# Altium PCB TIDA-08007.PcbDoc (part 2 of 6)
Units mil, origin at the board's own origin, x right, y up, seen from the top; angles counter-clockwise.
Board outline 4212.6 x 2047.24 mil, 10 copper layers (Top Layer, GND 1, Signal Layer 1, GND 2, Split PWR 1, Split PWR 2, GND 3, Signal Layer 2, GND 4, Bottom Layer), stack 66.4 mil thick; 291 components, 178 nets, 1281 pads, 873 vias.
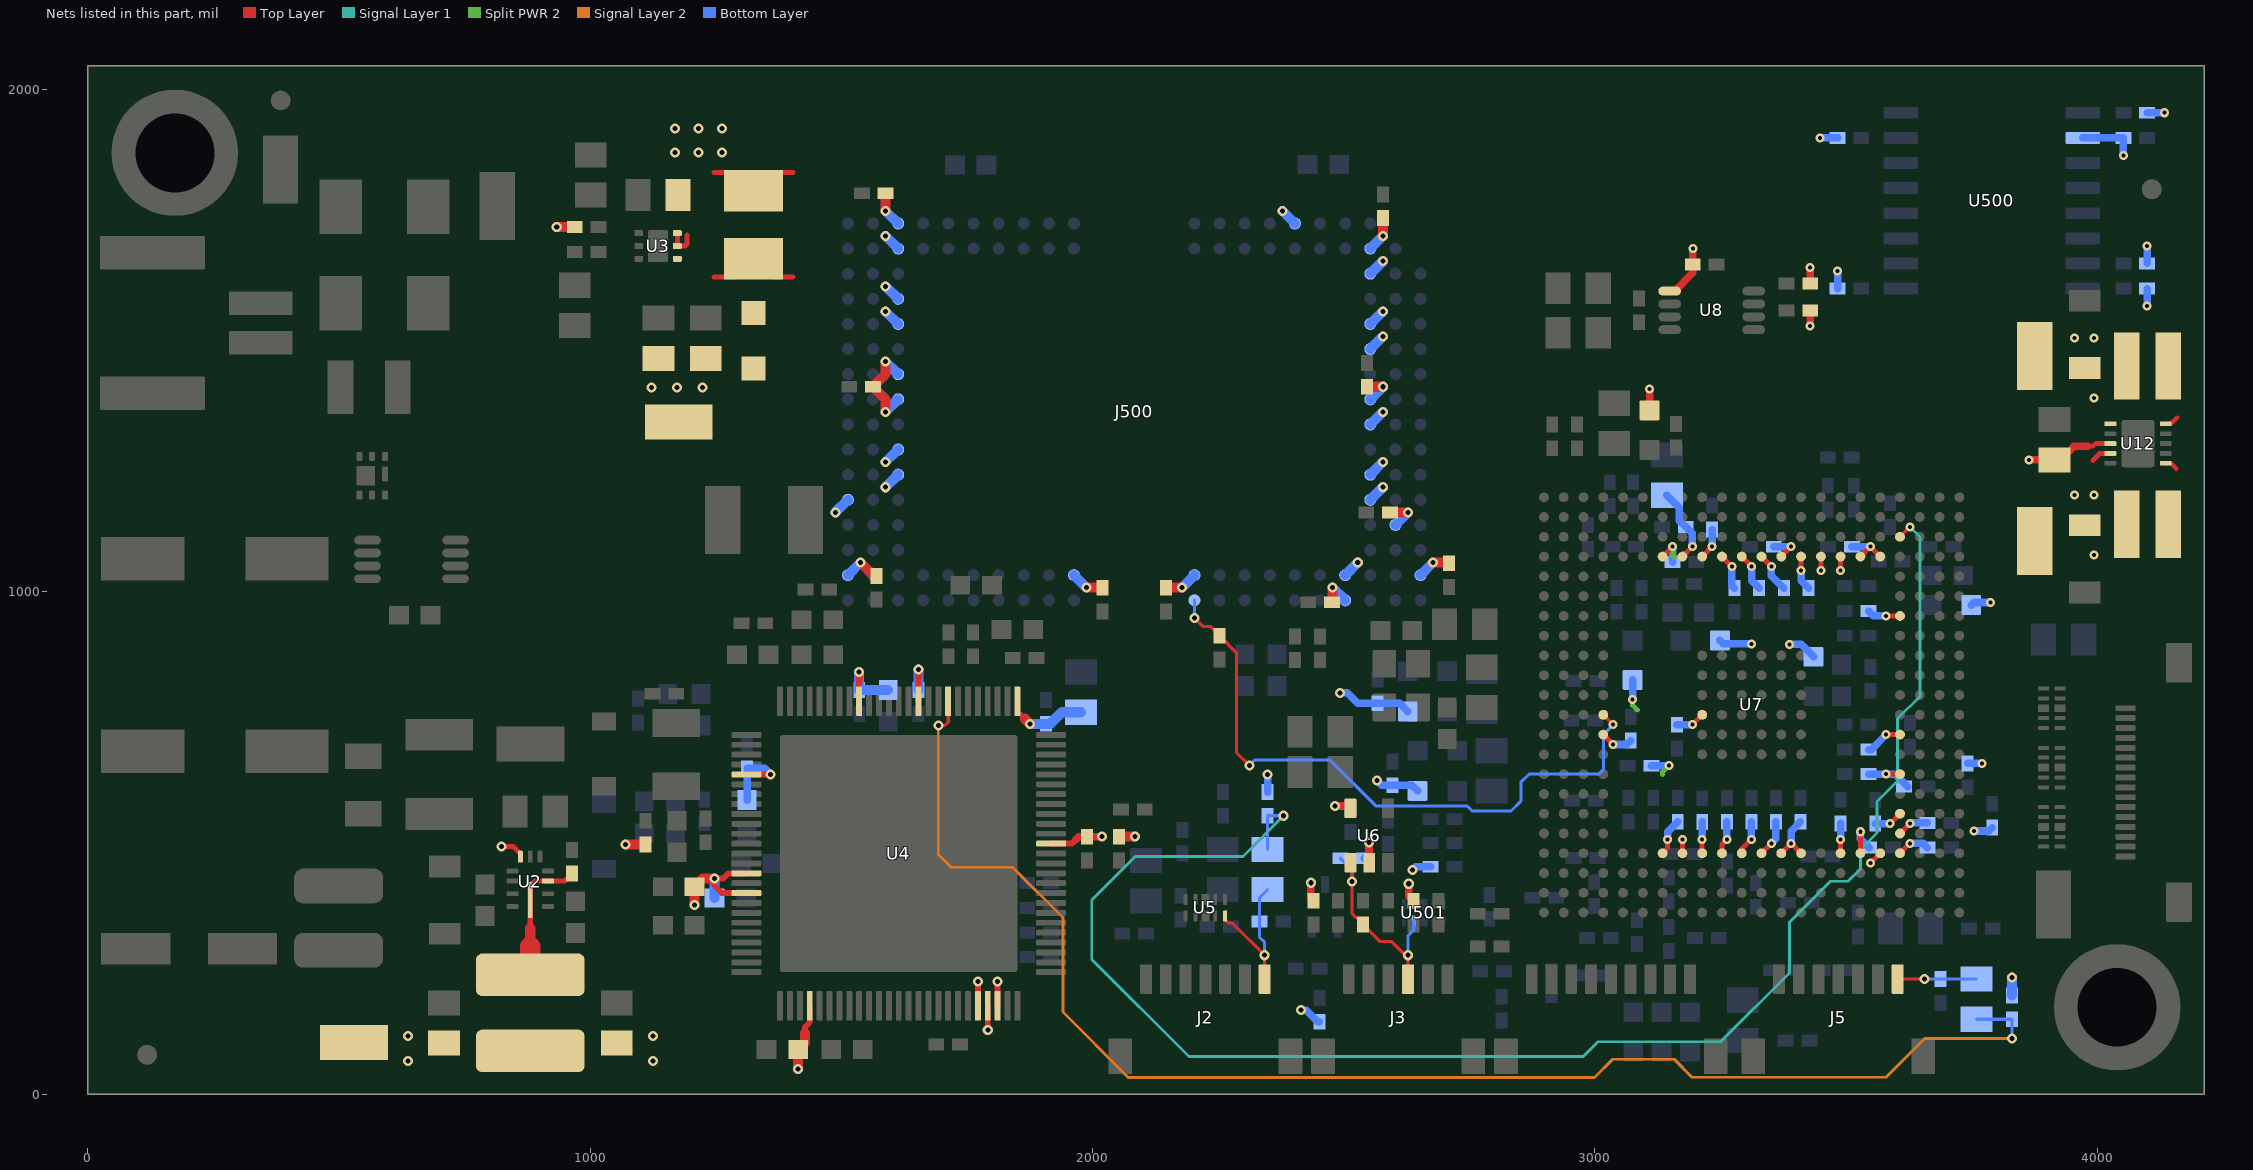
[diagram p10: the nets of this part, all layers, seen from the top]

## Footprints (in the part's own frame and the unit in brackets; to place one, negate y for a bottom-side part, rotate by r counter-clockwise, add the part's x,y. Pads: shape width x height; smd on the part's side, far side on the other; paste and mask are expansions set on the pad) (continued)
FP-450-2.700-L-13.25-149_SOCKET_CPGA149-MFG [mm]
  round 0.61 smd paste+0 mask+0: A3(-11.935,9.525) A4(-10.665,9.525) A5(-9.395,9.525) A6(-8.125,9.525) A7(-6.855,9.525) A8(-5.585,9.525) A9(-4.315,9.525) A10(-3.045,9.525) A11(3.045,9.525) A12(4.315,9.525) A13(5.585,9.525) A14(6.855,9.525) A15(8.125,9.525) A16(9.395,9.525) A17(10.665,9.525) A18(11.935,9.525) A19(13.205,9.525) A20(14.475,9.525) B2(-13.205,8.255) B3(-11.935,8.255) B4(-10.665,8.255) B5(-9.395,8.255) B6(-8.125,8.255) B7(-6.855,8.255) B8(-5.585,8.255) B9(-4.315,8.255) B10(-3.045,8.255) B11(3.045,8.255) B12(4.315,8.255) B13(5.585,8.255) B14(6.855,8.255) B15(8.125,8.255) B16(9.395,8.255) B17(10.665,8.255) B18(11.935,8.255) B19(13.205,8.255) B20(14.475,8.255) C1(-14.475,6.985) C2(-13.205,6.985) C3(-11.935,6.985) C18(11.935,6.985) C19(13.205,6.985) C20(14.475,6.985) D1(-14.475,5.715) D2(-13.205,5.715) D3(-11.935,5.715) D18(11.935,5.715) D19(13.205,5.715) D20(14.475,5.715) E1(-14.475,4.445) E2(-13.205,4.445) E3(-11.935,4.445) E18(11.935,4.445) E19(13.205,4.445) E20(14.475,4.445) F1(-14.475,3.175) F2(-13.205,3.175) F3(-11.935,3.175) F18(11.935,3.175) F19(13.205,3.175) F20(14.475,3.175) G1(-14.475,1.905) G2(-13.205,1.905) G3(-11.935,1.905) G18(11.935,1.905) G19(13.205,1.905) G20(14.475,1.905) H1(-14.475,0.635) H2(-13.205,0.635) H3(-11.935,0.635) H18(11.935,0.635) H19(13.205,0.635) H20(14.475,0.635) J1(-14.475,-0.635) J2(-13.205,-0.635) J3(-11.935,-0.635) J18(11.935,-0.635) J19(13.205,-0.635) J20(14.475,-0.635) K1(-14.475,-1.905) K2(-13.205,-1.905) K3(-11.935,-1.905) K18(11.935,-1.905) K19(13.205,-1.905) K20(14.475,-1.905) L1(-14.475,-3.175) L2(-13.205,-3.175) L3(-11.935,-3.175) L18(11.935,-3.175) L19(13.205,-3.175) L20(14.475,-3.175) M1(-14.475,-4.445) M2(-13.205,-4.445) M3(-11.935,-4.445) M18(11.935,-4.445) M19(13.205,-4.445) M20(14.475,-4.445) N1(-14.475,-5.715) N2(-13.205,-5.715) N3(-11.935,-5.715) N18(11.935,-5.715) N19(13.205,-5.715) N20(14.475,-5.715) P1(-14.475,-6.985) P2(-13.205,-6.985) P3(-11.935,-6.985) P18(11.935,-6.985) P19(13.205,-6.985) P20(14.475,-6.985) R1(-14.475,-8.255) R2(-13.205,-8.255) R3(-11.935,-8.255) R4(-10.665,-8.255) R5(-9.395,-8.255) R6(-8.125,-8.255) R7(-6.855,-8.255) R8(-5.585,-8.255) R9(-4.315,-8.255) R10(-3.045,-8.255) R11(3.045,-8.255) R12(4.315,-8.255) R13(5.585,-8.255) R14(6.855,-8.255) R15(8.125,-8.255) R16(9.395,-8.255) R17(10.665,-8.255) R18(11.935,-8.255) R19(13.205,-8.255) R20(14.475,-8.255) T1(-14.475,-9.525) T2(-13.205,-9.525) T3(-11.935,-9.525) T4(-10.665,-9.525) T5(-9.395,-9.525) T6(-8.125,-9.525) T7(-6.855,-9.525) T8(-5.585,-9.525) T9(-4.315,-9.525) T10(-3.045,-9.525) T11(3.045,-9.525) T12(4.315,-9.525) T13(5.585,-9.525) T14(6.855,-9.525) T15(8.125,-9.525) T16(9.395,-9.525) T17(10.665,-9.525) T18(11.935,-9.525) T19(13.205,-9.525) T20(14.475,-9.525)
  body extent -16.1,-11.15 16.1,11.15, height 2.9
FP-203559-0607_HDR6-MFG [mm]
  rrect17% 0.6x1.5 smd paste-1000 mask+0: 1(-2.5,2.825) 2(-1.5,2.825) 3(-0.5,2.825) 4(0.5,2.825) 5(1.5,2.825) 6(2.5,2.825)
  rrect8% 1.2x1.8 smd paste-1000 mask+0: 7(-3.8,-1.075) 8(3.8,-1.075)
  Top Layer keep-out region: -3.35,-2.975 3.35,-2.975 3.35,2.675 -3.35,2.675
  body extent -4.5,-2.98 4.5,3.67, height 0.25
FP-501568-0707_HDR7-MFG [mm]
  rrect17% 0.6x1.5 smd paste-1000 mask+0: 1(-3,2.825) 2(-2,2.825) 3(-1,2.825) 4(0,2.825) 5(1,2.825) 6(2,2.825) 7(3,2.825)
  rrect8% 1.2x1.8 smd paste-1000 mask+0: 8(-4.3,-1.075) 9(4.3,-1.075)
  Top Layer keep-out region: -3.85,-2.975 3.85,-2.975 3.85,2.675 -3.85,2.675
  body extent -5,-2.98 5,3.67, height 0.25
FP-501568-0907_HDR9-MFG [mm]
  rrect17% 0.6x1.5 smd paste-1000 mask+0: 1(-4,2.825) 2(-3,2.825) 3(-2,2.825) 4(-1,2.825) 5(0,2.825) 6(1,2.825) 7(2,2.825) 8(3,2.825) 9(4,2.825)
  rrect8% 1.2x1.8 smd paste-1000 mask+0: 10(-5.3,-1.075) 11(5.3,-1.075)
  Top Layer keep-out region: -4.85,-2.975 4.85,-2.975 4.85,2.675 -4.85,2.675
  body extent -6,-2.98 6,3.67, height 0.25
FP-502352-0200_HDR2-MFG [mm]
  rrect8% 1.2x3.2 smd paste+0 mask+0: 1(-1,3.53) 2(1,3.53)
  rrect6% 1.7x5.3 smd paste+0 mask+0: 3(-3.55,-1.95) 4(3.55,-1.95)
  body extent -4.5,-4.9 4.5,5.23, height 0.25
FP-505110-1692_CONN_SMT_12MM7_5MM25-MFG [mm]
  rrect33% 0.3x1 smd paste+0 mask+0: 1(-3.75,2.475) 2(-3.25,2.475) 3(-2.75,2.475) 4(-2.25,2.475) 5(-1.75,2.475) 6(-1.25,2.475) 7(-0.75,2.475) 8(-0.25,2.475) 9(0.25,2.475) 10(0.75,2.475) 11(1.25,2.475) 12(1.75,2.475) 13(2.25,2.475) 14(2.75,2.475) 15(3.25,2.475) 16(3.75,2.475)
  rrect8% 2x1.3 smd paste+0 mask+0: 17(-6.05,-0.225) 18(6.05,-0.225)
  body extent -7.15,-2.83 7.15,3.08, height 0.25
FP-AM16070006_SMT_XTAL_3MM2_2MM5-MFG [mm]
  rrect8% 1.4x1.2 smd paste+0 mask+0: 1(-1.1,-0.85) 2(1.1,-0.85) 3(1.1,0.85) 4(-1.1,0.85)
  body extent -1.6,-1.25 1.6,1.25, height 0.8
FP-FBMH1608HM101-TV_0603-MFG [mm]
  rrect10% 1x1 smd paste+0 mask+0: 1(-1,0) 2(1,0)
  body extent -0.8,-0.4 0.8,0.4, height 0.9
FP-MT25QL128ABA8ESF-0AAT_SOP2-16-MFG [mm]
  rrect17% 1.75x0.6 smd paste+0 mask+0: 1(-4.6,4.445) 2(-4.6,3.175) 3(-4.6,1.905) 4(-4.6,0.635) 5(-4.6,-0.635) 6(-4.6,-1.905) 7(-4.6,-3.175) 8(-4.6,-4.445) 9(4.6,-4.445) 10(4.6,-3.175) 11(4.6,-1.905) 12(4.6,-0.635) 13(4.6,0.635) 14(4.6,1.905) 15(4.6,3.175) 16(4.6,4.445)
  body extent -5.16,-5.15 5.16,5.15, height 2.65
MTGP_252mil_157mil_6Via [mil] "4-40 Mounting Hole, Plated, for Pan Head"
  round 252 hole 157: 1(0,0)
PZP0100K [mm] "TQFP-100"
  rrect33% 1.5x0.3 smd: 1(-7.7,6) 2(-7.7,5.5) 3(-7.7,5) 4(-7.7,4.5) 5(-7.7,4) 6(-7.7,3.5) 7(-7.7,3) 8(-7.7,2.5) 9(-7.7,2) 10(-7.7,1.5) 11(-7.7,1) 12(-7.7,0.5) 13(-7.7,0) 14(-7.7,-0.5) 15(-7.7,-1) 16(-7.7,-1.5) 17(-7.7,-2) 18(-7.7,-2.5) 19(-7.7,-3) 20(-7.7,-3.5) 21(-7.7,-4) 22(-7.7,-4.5) 23(-7.7,-5) 24(-7.7,-5.5) 25(-7.7,-6) 51(7.7,-6) 52(7.7,-5.5) 53(7.7,-5) 54(7.7,-4.5) 55(7.7,-4) 56(7.7,-3.5) 57(7.7,-3) 58(7.7,-2.5) 59(7.7,-2) 60(7.7,-1.5) 61(7.7,-1) 62(7.7,-0.5) 63(7.7,0) 64(7.7,0.5) 65(7.7,1) 66(7.7,1.5) 67(7.7,2) 68(7.7,2.5) 69(7.7,3) 70(7.7,3.5) 71(7.7,4) 72(7.7,4.5) 73(7.7,5) 74(7.7,5.5) 75(7.7,6)
  rrect33% 0.3x1.5 smd: 26(-6,-7.7) 27(-5.5,-7.7) 28(-5,-7.7) 29(-4.5,-7.7) 30(-4,-7.7) 31(-3.5,-7.7) 32(-3,-7.7) 33(-2.5,-7.7) 34(-2,-7.7) 35(-1.5,-7.7) 36(-1,-7.7) 37(-0.5,-7.7) 38(0,-7.7) 39(0.5,-7.7) 40(1,-7.7) 41(1.5,-7.7) 42(2,-7.7) 43(2.5,-7.7) 44(3,-7.7) 45(3.5,-7.7) 46(4,-7.7) 47(4.5,-7.7) 48(5,-7.7) 49(5.5,-7.7) 50(6,-7.7) 76(6,7.7) 77(5.5,7.7) 78(5,7.7) 79(4.5,7.7) 80(4,7.7) 81(3.5,7.7) 82(3,7.7) 83(2.5,7.7) 84(2,7.7) 85(1.5,7.7) 86(1,7.7) 87(0.5,7.7) 88(0,7.7) 89(-0.5,7.7) 90(-1,7.7) 91(-1.5,7.7) 92(-2,7.7) 93(-2.5,7.7) 94(-3,7.7) 95(-3.5,7.7) 96(-4,7.7) 97(-4.5,7.7) 98(-5,7.7) 99(-5.5,7.7) 100(-6,7.7)
  rrect2% 12x12 smd paste-3 mask-3: 101(0,0)
  body extent -8.01,-8.01 8.01,8.01, height 1.2
RNX0012B [mm] "VQFN-HR-12"
  rrect40% 0.6x0.25 smd: 1(-0.9,1.125) 2(-0.9,0.475) 3(-0.9,-0.175) 4(-0.9,-0.675) 8(0.9,-0.675) 9(0.9,-0.175) 10(0.9,0.475) 11(0.9,1.125)
  rrect40% 0.25x0.6 smd: 5(-0.5,-1.4) 6(0,-1.4) 7(0.5,-1.4)
  rrect40% 0.25x1.825 smd paste-0.175: 12(0,0.788)
  body extent -1,-1.5 1,1.5, height 1
SDE0604A [mm] "BOURNS"
  rrect30% 2.15x5.5 smd: 1(-1.925,0) 2(1.925,0)
  Top Layer region: -0.9,2.75 -1.525,2.75 -1.544,2.746 -1.56,2.735 -1.571,2.719 -1.575,2.7 -1.575,2.7 -1.575,2.5 -1.571,2.481 -1.56,2.465 -1.544,2.454 -1.525,2.45 -1.525,2.45 -0.9,2.45 -0.881,2.454 -0.865,2.465 -0.854,2.481 -0.85,2.5 -0.85,2.5 -0.85,2.7 -0.854,2.719 -0.865,2.735 -0.881,2.746 -0.9,2.75
  Top Layer region: 0.9,2.75 1.525,2.75 1.544,2.746 1.56,2.735 1.571,2.719 1.575,2.7 1.575,2.7 1.575,2.5 1.571,2.481 1.56,2.465 1.544,2.454 1.525,2.45 1.525,2.45 0.9,2.45 0.881,2.454 0.865,2.465 0.854,2.481 0.85,2.5 0.85,2.5 0.85,2.7 0.854,2.719 0.865,2.735 0.881,2.746 0.9,2.75
  Top Layer region: 0.9,-2.75 1.525,-2.75 1.544,-2.746 1.56,-2.735 1.571,-2.719 1.575,-2.7 1.575,-2.7 1.575,-2.5 1.571,-2.481 1.56,-2.465 1.544,-2.454 1.525,-2.45 1.525,-2.45 0.9,-2.45 0.881,-2.454 0.865,-2.465 0.854,-2.481 0.85,-2.5 0.85,-2.5 0.85,-2.7 0.854,-2.719 0.865,-2.735 0.881,-2.746 0.9,-2.75
  Top Layer region: -0.898,-2.75 -1.523,-2.75 -1.542,-2.746 -1.558,-2.735 -1.569,-2.719 -1.573,-2.7 -1.572,-2.7 -1.573,-2.5 -1.569,-2.481 -1.558,-2.465 -1.542,-2.454 -1.523,-2.45 -1.523,-2.45 -0.898,-2.45 -0.878,-2.454 -0.862,-2.465 -0.851,-2.481 -0.848,-2.5 -0.848,-2.5 -0.847,-2.7 -0.851,-2.719 -0.862,-2.735 -0.878,-2.746 -0.898,-2.75
  Top Layer region: -0.85,2.072 -1.05,2.073 -1.05,2.648 -0.85,2.648
  Top Layer region: 0.85,2.043 1.05,2.043 1.05,2.618 0.85,2.618
  Top Layer region: 0.85,-2.102 1.05,-2.103 1.05,-2.678 0.85,-2.678
  Top Layer region: -0.85,-2.143 -1.05,-2.142 -1.05,-2.718 -0.85,-2.718
  silkscreen extent -0.63,-2.84 0.62,2.85, body extent -3.05,-2.74 3.05,2.74, height 4.8
SMB [mil] "Molded Diode, 2-Leads, Body 5.4x3.6mm, IPC Medium Density, based on OnSemi component dimensions"
  rect 85x107.99 smd: 1(-87.01,0) 2(87.01,0)
  silkscreen extent -155,-82 125,82, body extent -106,-71 106,71, height 91
SOD-123 [mm] "On Semi recommended land pattern"
  rect 0.915x1.22 smd: 1(-1.637,0) 2(1.637,0)
  silkscreen extent -2.74,-1.17 2.03,1.17, body extent -1.93,-0.9 1.93,0.9, height 1.35
SOD-123F [mm] "NXP recommended land pattern"
  rect 1.2x1.2 smd paste-0.05: 1(-1.4,0) 2(1.4,0)
  silkscreen extent -2.64,-1.12 2.01,1.12, body extent -1.8,-0.85 1.8,0.85, height 1.2
Testpoint_Keystone_Miniature [mil] "Miniature SMT test point"
  rect 135x70 smd: 1(0,0)
  silkscreen extent -78,-46 78,45, body extent -52,-20 52,20, height 61
TI_Stacked_Overlay_Small [mil]
  silkscreen extent -418,-98 418,98
VLCF5020 [mm] "TDK"
  rect 2.1x3 smd: 1(-1.725,0) 2(1.725,0)
  Top Layer region: -0.675,2.45 -1.875,2.45 -2.775,1.55 -2.775,1.4 -0.675,1.4
  Top Layer region: -0.675,-2.45 -1.875,-2.45 -2.775,-1.55 -2.775,-1.4 -0.675,-1.4
  Top Layer region: 0.675,-2.45 1.875,-2.45 2.775,-1.55 2.775,-1.4 0.675,-1.4
  Top Layer region: 0.675,2.4 1.875,2.4 2.775,1.5 2.775,1.35 0.675,1.35
  body extent -2.6,-2.6 2.6,2.6, height 2
WE-MAIA_3015 [mm] "SMD, 2-Leads, Body 3x3mm"
  rect 1.3x3.4 smd: 1(-1.05,0) 2(1.05,0)
  silkscreen extent -0.1,-1.6 0.1,1.6, body extent -1.6,-1.6 1.6,1.6, height 1.5
WE-PD2-S [mm] "WURTH"
  rrect50% 1.75x4.5 smd: 1(-1.625,0) 2(1.625,0)
  Top Layer region: 1.375,2.25 0.75,2.25 0.75,-2.25 1.375,-2.25
  Top Layer region: -1.375,-2.25 -0.75,-2.25 -0.75,2.25 -1.375,2.25
  silkscreen extent -0.4,-2.1 0.4,2.12, body extent -2.25,-2 2.25,2, height 3.18
WEEE_Minimum [mil] "WEEElie bin"
  silkscreen extent -95,-172 99,104
ZDQ0324 [mm] "BGA-324"
  round 0.5 smd: A1(-10.5,10.5) A2(-9.5,10.5) A3(-8.5,10.5) A4(-7.5,10.5) A5(-6.5,10.5) A6(-5.5,10.5) A7(-4.5,10.5) A8(-3.5,10.5) A9(-2.5,10.5) A10(-1.5,10.5) A11(-0.5,10.5) A12(0.5,10.5) A13(1.5,10.5) A14(2.5,10.5) A15(3.5,10.5) A16(4.5,10.5) A17(5.5,10.5) A18(6.5,10.5) A19(7.5,10.5) A20(8.5,10.5) A21(9.5,10.5) A22(10.5,10.5) AA1(-10.5,-9.5) AA2(-9.5,-9.5) AA3(-8.5,-9.5) AA4(-7.5,-9.5) AA5(-6.5,-9.5) AA6(-5.5,-9.5) AA7(-4.5,-9.5) AA8(-3.5,-9.5) AA9(-2.5,-9.5) AA10(-1.5,-9.5) AA11(-0.5,-9.5) AA12(0.5,-9.5) AA13(1.5,-9.5) AA14(2.5,-9.5) AA15(3.5,-9.5) AA16(4.5,-9.5) AA17(5.5,-9.5) AA18(6.5,-9.5) AA19(7.5,-9.5) AA20(8.5,-9.5) AA21(9.5,-9.5) AA22(10.5,-9.5) AB1(-10.5,-10.5) AB2(-9.5,-10.5) AB3(-8.5,-10.5) AB4(-7.5,-10.5) AB5(-6.5,-10.5) AB6(-5.5,-10.5) AB7(-4.5,-10.5) AB8(-3.5,-10.5) AB9(-2.5,-10.5) AB10(-1.5,-10.5) AB11(-0.5,-10.5) AB12(0.5,-10.5) AB13(1.5,-10.5) AB14(2.5,-10.5) AB15(3.5,-10.5) AB16(4.5,-10.5) AB17(5.5,-10.5) AB18(6.5,-10.5) AB19(7.5,-10.5) AB20(8.5,-10.5) AB21(9.5,-10.5) AB22(10.5,-10.5) B1(-10.5,9.5) B2(-9.5,9.5) B3(-8.5,9.5) B4(-7.5,9.5) B5(-6.5,9.5) B6(-5.5,9.5) B7(-4.5,9.5) B8(-3.5,9.5) B9(-2.5,9.5) B10(-1.5,9.5) B11(-0.5,9.5) B12(0.5,9.5) B13(1.5,9.5) B14(2.5,9.5) B15(3.5,9.5) B16(4.5,9.5) B17(5.5,9.5) B18(6.5,9.5) B19(7.5,9.5) B20(8.5,9.5) B21(9.5,9.5) B22(10.5,9.5) C1(-10.5,8.5) C2(-9.5,8.5) C3(-8.5,8.5) C4(-7.5,8.5) C5(-6.5,8.5) C6(-5.5,8.5) C7(-4.5,8.5) C8(-3.5,8.5) C9(-2.5,8.5) C10(-1.5,8.5) C11(-0.5,8.5) C12(0.5,8.5) C13(1.5,8.5) C14(2.5,8.5) C15(3.5,8.5) C16(4.5,8.5) C17(5.5,8.5) C18(6.5,8.5) C19(7.5,8.5) C20(8.5,8.5) C21(9.5,8.5) C22(10.5,8.5) D1(-10.5,7.5) D2(-9.5,7.5) D3(-8.5,7.5) D4(-7.5,7.5) D5(-6.5,7.5) D6(-5.5,7.5) D7(-4.5,7.5) D8(-3.5,7.5) D9(-2.5,7.5) D10(-1.5,7.5) D11(-0.5,7.5) D12(0.5,7.5) D13(1.5,7.5) D14(2.5,7.5) D15(3.5,7.5) D16(4.5,7.5) D17(5.5,7.5) D18(6.5,7.5) D19(7.5,7.5) D20(8.5,7.5) D21(9.5,7.5) D22(10.5,7.5) E1(-10.5,6.5) E2(-9.5,6.5) E3(-8.5,6.5) E4(-7.5,6.5) E19(7.5,6.5) E20(8.5,6.5) E21(9.5,6.5) E22(10.5,6.5) F1(-10.5,5.5) F2(-9.5,5.5) F3(-8.5,5.5) F4(-7.5,5.5) F19(7.5,5.5) F20(8.5,5.5) F21(9.5,5.5) F22(10.5,5.5) G1(-10.5,4.5) G2(-9.5,4.5) G3(-8.5,4.5) G4(-7.5,4.5) G19(7.5,4.5) G20(8.5,4.5) G21(9.5,4.5) G22(10.5,4.5) H1(-10.5,3.5) H2(-9.5,3.5) H3(-8.5,3.5) H4(-7.5,3.5) H19(7.5,3.5) H20(8.5,3.5) H21(9.5,3.5) H22(10.5,3.5) J1(-10.5,2.5) J2(-9.5,2.5) J3(-8.5,2.5) J4(-7.5,2.5) J9(-2.5,2.5) J10(-1.5,2.5) J11(-0.5,2.5) J12(0.5,2.5) J13(1.5,2.5) J14(2.5,2.5) J19(7.5,2.5) J20(8.5,2.5) J21(9.5,2.5) J22(10.5,2.5) K1(-10.5,1.5) K2(-9.5,1.5) K3(-8.5,1.5) K4(-7.5,1.5) K9(-2.5,1.5) K10(-1.5,1.5) K11(-0.5,1.5) K12(0.5,1.5) K13(1.5,1.5) K14(2.5,1.5) K19(7.5,1.5) K20(8.5,1.5) K21(9.5,1.5) K22(10.5,1.5) L1(-10.5,0.5) L2(-9.5,0.5) L3(-8.5,0.5) L4(-7.5,0.5) L9(-2.5,0.5) L10(-1.5,0.5) L11(-0.5,0.5) L12(0.5,0.5) L13(1.5,0.5) L14(2.5,0.5) L19(7.5,0.5) L20(8.5,0.5) L21(9.5,0.5) L22(10.5,0.5) M1(-10.5,-0.5) M2(-9.5,-0.5) M3(-8.5,-0.5) M4(-7.5,-0.5) M9(-2.5,-0.5) M10(-1.5,-0.5) M11(-0.5,-0.5) M12(0.5,-0.5) M13(1.5,-0.5) M14(2.5,-0.5) M19(7.5,-0.5) M20(8.5,-0.5) M21(9.5,-0.5) M22(10.5,-0.5) N1(-10.5,-1.5) N2(-9.5,-1.5) N3(-8.5,-1.5) N4(-7.5,-1.5) N9(-2.5,-1.5) N10(-1.5,-1.5) N11(-0.5,-1.5) N12(0.5,-1.5) N13(1.5,-1.5) N14(2.5,-1.5) N19(7.5,-1.5) N20(8.5,-1.5) N21(9.5,-1.5) N22(10.5,-1.5) P1(-10.5,-2.5) P2(-9.5,-2.5) P3(-8.5,-2.5) P4(-7.5,-2.5) P9(-2.5,-2.5) P10(-1.5,-2.5) P11(-0.5,-2.5) P12(0.5,-2.5) P13(1.5,-2.5) P14(2.5,-2.5) P19(7.5,-2.5) P20(8.5,-2.5) P21(9.5,-2.5) P22(10.5,-2.5) R1(-10.5,-3.5) R2(-9.5,-3.5) R3(-8.5,-3.5) R4(-7.5,-3.5) R19(7.5,-3.5) R20(8.5,-3.5) R21(9.5,-3.5) R22(10.5,-3.5) T1(-10.5,-4.5) T2(-9.5,-4.5) T3(-8.5,-4.5) T4(-7.5,-4.5) T19(7.5,-4.5) T20(8.5,-4.5) T21(9.5,-4.5) T22(10.5,-4.5) U1(-10.5,-5.5) U2(-9.5,-5.5) U3(-8.5,-5.5) U4(-7.5,-5.5) U19(7.5,-5.5) U20(8.5,-5.5) U21(9.5,-5.5) U22(10.5,-5.5) V1(-10.5,-6.5) V2(-9.5,-6.5) V3(-8.5,-6.5) V4(-7.5,-6.5) V19(7.5,-6.5) V20(8.5,-6.5) V21(9.5,-6.5) V22(10.5,-6.5) W1(-10.5,-7.5) W2(-9.5,-7.5) W3(-8.5,-7.5) W4(-7.5,-7.5) W5(-6.5,-7.5) W6(-5.5,-7.5) W7(-4.5,-7.5) W8(-3.5,-7.5) W9(-2.5,-7.5) W10(-1.5,-7.5) W11(-0.5,-7.5) W12(0.5,-7.5) W13(1.5,-7.5) W14(2.5,-7.5) W15(3.5,-7.5) W16(4.5,-7.5) W17(5.5,-7.5) W18(6.5,-7.5) W19(7.5,-7.5) W20(8.5,-7.5) W21(9.5,-7.5) W22(10.5,-7.5) Y1(-10.5,-8.5) Y2(-9.5,-8.5) Y3(-8.5,-8.5) Y4(-7.5,-8.5) Y5(-6.5,-8.5) Y6(-5.5,-8.5) Y7(-4.5,-8.5) Y8(-3.5,-8.5) Y9(-2.5,-8.5) Y10(-1.5,-8.5) Y11(-0.5,-8.5) Y12(0.5,-8.5) Y13(1.5,-8.5) Y14(2.5,-8.5) Y15(3.5,-8.5) Y16(4.5,-8.5) Y17(5.5,-8.5) Y18(6.5,-8.5) Y19(7.5,-8.5) Y20(8.5,-8.5) Y21(9.5,-8.5) Y22(10.5,-8.5)
  body extent -11.5,-11.5 11.5,11.5, height 2.35

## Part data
C1 C2: library part CMP-0086092-1, "CAP, AL, 220 µF, 50 V, +/- 20%, AEC-Q200 Grade 2, SMD", Cap_Case=HA0, Manufacturer=Chemi-Con, Tolerance_%=20%, Value2=50V, ValueDisplayed=220µF
C3: library part CMP-0011237-3, "CAP, AL, 22 uF, 50 V, +/- 20%, SMD", Cap_Case=F55, Manufacturer=Chemi-Con, Supplier Part Number 1=565-2130-1-ND, Tolerance_%=20%, Value1=Unknown, Value2=50V, ValueDisplayed=22uF
C4: library part CMP-0079201-1, "CAP, CERM, 10 µF, 50 V,+/- 10%, X7R, 1210", Cap_Case=1210, Manufacturer="Samsung Electro-Mechanics", Supplier Part Number 1=1276-3388-1-ND, TempCo=X7R, Tolerance_%=10%, Value1="0.005 ohm", Value2=50V, ValueDisplayed=10µF
C5 C18 C19 C20 C24 C27 C501 C522 C535 C579 C581 C582 C583: library part CMP-0064934-4, "CAP, CERM, 2.2 uF, 16 V,+/- 10%, X7R, 0603", Cap_Case=0603, Manufacturer="Taiyo Yuden", Supplier Part Number 1=587-4864-1-ND, TempCo=X7R, Tolerance_%=10%, Value1=Unknown, Value2=16V, ValueDisplayed=2.2uF
C6: library part CMP-0860184-1, "CAP, CERM, 6.8 µF, 50 V,+/- 20%, X7R, 1812", Cap_Case=1812, Manufacturer=TDK, TempCo=X7R, Tolerance_%=20%, Value2=50V, ValueDisplayed=6.8µF
C7 C14: library part CMP-0007851-1, "CAP, CERM, 15 uF, 16 V, +/- 20%, X6S, 0805", Cap_Case=0805, Manufacturer=TDK, Supplier Part Number 1=445-14485-1-ND, TempCo=X6S, Tolerance_%=20%, Value1="0.001669 ohm", Value2=16V, ValueDisplayed=15uF
C8: library part CMP-0085643-1, "CAP, CERM, 4.7 µF, 50 V,+/- 10%, X7S, AEC-Q200 Grade 1, 1206", Cap_Case=1206, Manufacturer=MuRata, TempCo=X7S, Tolerance_%=10%, Value2=50V, ValueDisplayed=4.7µF
C9 C13: library part CMP-0006901-4, "CAP, CERM, 0.022 uF, 50 V, +/- 10%, X7R, 0603", Cap_Case=0603, Manufacturer=Kemet, Supplier Part Number 1=399-1280-1-ND, TempCo=X7R, Tolerance_%=10%, Value1=Unknown, Value2=50V, ValueDisplayed=0.022uF
C10: library part CMP-0008397-2, "CAP, CERM, 1 uF, 10 V, +/- 10%, X7R, 0805", Cap_Case=0805, Manufacturer="Taiyo Yuden", Supplier Part Number 1=587-1285-1-ND, TempCo=X7R, Tolerance_%=10%, Value1=Unknown, Value2=10V, ValueDisplayed=1uF
C11: library part CMP-0007639-2, "CAP, CERM, 0.015 uF, 50 V, +/- 10%, X7R, 0805", Cap_Case=0805, Manufacturer=AVX, Supplier Part Number 1=478-1385-1-ND, TempCo=X7R, Tolerance_%=10%, Value1="0.063 ohm", Value2=50V, ValueDisplayed=0.015uF
C12 C22 C28 C29 C30 C31 C34 C35 C36 C37 C40 C41 C43 C47 C48 C49 C52 C500 C502 C503 C504 C506 C507 C508 C509 C510 C511 C512 C513 C514 C515 C516 C517 C518 C520 C523 C524 C525 C527 C528 C529 C530 C531 C532 C533 C534 C536 C537 C538 C539 C540 C541 C543 C544 C545 C546 C547 C548 C549 C551 C552 C553 C554 C555 C556 C558 C559 C564 C565 C566 C576 C578 C580 C584: library part CMP-0080702-1, "CAP, CERM, 0.1 µF, 16 V,+/- 5%, X7R, AEC-Q200 Grade 1, 0402", Cap_Case=0402, Manufacturer=MuRata, Supplier Part Number 1=490-16433-1-ND, TempCo=X7R, Tolerance_%=5%, Value2=16V, ValueDisplayed=0.1µF
C15 C16 C21 C50 C53 C542 C575: library part CMP-0007864-2, "CAP, CERM, 10 uF, 10 V, +/- 20%, X7R, 0805", Cap_Case=0805, Manufacturer=TDK, Supplier Part Number 1=445-7592-1-ND, TempCo=X7R, Tolerance_%=20%, Value1=Unknown, Value2=10V, ValueDisplayed=10uF
C17: library part CMP-0006687-2, "CAP, CERM, 330 pF, 50 V, +/- 10%, X7R, 0402", Cap_Case=0402, Manufacturer=MuRata, Supplier Part Number 1=490-3247-1-ND, TempCo=X7R, Tolerance_%=10%, Value1=Unknown, Value2=50V, ValueDisplayed=330pF
C23: library part CMP-0007424-4, "CAP, CERM, 0.47 uF, 25 V, +/- 10%, X7R, 0603", Cap_Case=0603, Manufacturer=MuRata, Supplier Part Number 1=490-3291-1-ND, TempCo=X7R, Tolerance_%=10%, Value1=Unknown, Value2=25V, ValueDisplayed=0.47uF
C25 C587: library part CMP-0007139-4, "CAP, CERM, 1 uF, 25 V, +/- 10%, X7R, AEC-Q200 Grade 1, 0603", Cap_Case=0603, Manufacturer=MuRata, Supplier Part Number 1=490-10673-1-ND, TempCo=X7R, Tolerance_%=10%, Value1=Unknown, Value2=25V, ValueDisplayed=1uF
C26 C32 C33 C567 C570 C571 C577 C585: library part CMP-0007145-4, "CAP, CERM, 0.22 uF, 50 V, +/- 10%, X7R, AEC-Q200 Grade 1, 0603", Cap_Case=0603, Manufacturer=MuRata, Supplier Part Number 1=490-5402-1-ND, TempCo=X7R, Tolerance_%=10%, Value1=Unknown, Value2=50V, ValueDisplayed=0.22uF
C38 C505 C519 C521 C526 C550 C557 C560 C561 C568 C569 C572 C573 C574: library part CMP-0006311-2, "CAP, CERM, 22 pF, 50 V, +/- 5%, C0G/NP0, AEC-Q200 Grade 1, 0402", Cap_Case=0402, Manufacturer=TDK, Supplier Part Number 1=445-12130-1-ND, TempCo=C0G/NP0, Tolerance_%=5%, Value1=Unknown, Value2=50V, ValueDisplayed=22pF
C39 C44 C45: library part CMP-0006646-2, "CAP, CERM, 2200 pF, 16 V, +/- 10%, X7R, 0402", Cap_Case=0402, Manufacturer=MuRata, Supplier Part Number 1=GRM155R71C222KA01D-ND, TempCo=X7R, Tolerance_%=10%, Value1=Unknown, Value2=16V, ValueDisplayed=2200pF
C42 C46: library part CMP-0007126-4, "CAP, CERM, 15 pF, 50 V, +/- 5%, C0G/NP0, AEC-Q200 Grade 1, 0603", Cap_Case=0603, Manufacturer=MuRata, Supplier Part Number 1=490-4957-1-ND, TempCo=C0G/NP0, Tolerance_%=5%, Value1=Unknown, Value2=50V, ValueDisplayed=15pF
C51: library part CMP-0006308-2, "CAP, CERM, 100 pF, 50 V, +/- 5%, C0G/NP0, AEC-Q200 Grade 1, 0402", Cap_Case=0402, Manufacturer=TDK, Supplier Part Number 1=445-5596-1-ND, TempCo=C0G/NP0, Tolerance_%=5%, Value1=Unknown, Value2=50V, ValueDisplayed=100pF
C54 C55: library part CMP-0008770-2, "CAP, CERM, 22 uF, 6.3 V, +/- 10%, X7R, AEC-Q200 Grade 1, 1206", Cap_Case=1206_180, Manufacturer=TDK, Supplier Part Number 1=445-7884-1-ND, TempCo=X7R, Tolerance_%=10%, Value1="0.001872 ohm", Value2=6.3V, ValueDisplayed=22uF
C562 C563: library part CMP-0085180-1, "CAP, CERM, 1 µF, 16 V,+/- 10%, X7R, AEC-Q200 Grade 1, 0805", Cap_Case=0805, Manufacturer=MuRata, TempCo=X7R, Tolerance_%=10%, Value2=16V, ValueDisplayed=1µF
C586: library part CMP-0006322-2, "CAP, CERM, 680 pF, 50 V, +/- 10%, X7R, AEC-Q200 Grade 1, 0402", Cap_Case=0402, Manufacturer=TDK, Supplier Part Number 1=445-6889-1-ND, TempCo=X7R, Tolerance_%=10%, Value1="3.07785 ohm", Value2=50V, ValueDisplayed=680pF
D1: library part CMP-0005557-4, "Diode, TVS, Uni, 24 V, 38.9 Vc, SMB", Manufacturer="Diodes Inc.", Value1=600W
D2: library part CMP-0005547-4, "Diode, TVS, Uni, 16 V, 26 Vc, SMB", Manufacturer="Diodes Inc.", Value1=600W
D3: library part CMP-0028526-2, "Diode, Schottky, 40 V, 0.5 A, SOD-123", Manufacturer="ON Semiconductor", Value1=0.5A, Value2=0.51V
D4: library part CMP-0028797-2, "Diode, Schottky, 20 V, 1 A, SOD-123F", Manufacturer="Fairchild Semiconductor", Value1=1A, Value2=0.34V
D500: library part CMP-0005805-3, "Diode, Zener, 6.2 V, 500 mW, SOD-123", Manufacturer="Diodes Inc.", Power_W=500mW, Value1=0.5W
FB1 FB500 FB501 FB502 FB503 FB504 FB505 FB507 FB508 FB509 FB510: library part CMP-0086561-1, "Ind Chip Bead Multi-Layer 100Ohm 25% 100MHz Ferrite 2.5A 0603 T/R", Manufacturer="Taiyo Yuden"
FB506: library part CMP-0086561-1, "Ind Chip Bead Multi-Layer 100Ohm 25% 100MHz Ferrite 2.5A 0603 T/R", Manufacturer="Taiyo Yuden", PartNumber=FBMH1608HM101-TV
FID1 FID2 FID3 FID500 FID501 FID502: library part CMP-0077181-1, "Fiducial mark.  There is nothing to buy or mount.", Manufacturer=N/A
J1: library part CMP-0087312-1, "CONN HEADER SMD R/A 2POS 2MM", Current_A=3A, Manufacturer=Molex, Voltage_V=125V
J2 J5: library part CMP-0087313-1, "CONN HEADER 1MM 7POS SMD R/A", Current_A=1A, Manufacturer=Molex, Voltage_V=50V
J3: library part CMP-0087314-1, "CONN HEADER SMD R/A 6POS 1MM", Current_A=1A, Manufacturer=Molex, Voltage_V=50V
J4: library part CMP-0086592-1, "CONN HEADER SMD R/A 9POS 1MM", Current_A=1A, Manufacturer=Molex, Voltage_V=50V
J6: library part CMP-0086503-1, "CONN FPC BOTTOM 16POS .5MM R/A", Current_A=500mA, Manufacturer=Molex, Voltage_V=50V
J500: library part CMP-0087054-2, "Socket Assembly for DLP5531", DUT-PackageType=CPGA149, Manufacturer="Texas Instruments"
L1: library part CMP-0064234-1, "Inductor, Unshielded Drum Core, Metal Composite, 3.9 uH, 1.88 A, 0.054 ohm, SMD", Manufacturer="Wurth Elektronik", Supplier Part Number 1=732-1251-1-ND, Value1="0.054 ohm", Value2=1.88A, ValueDisplayed=3.9uH
L2: library part CMP-0003113-1, "Ferrite Bead, 50 ohm @ 100 MHz, 3 A, 1206", Manufacturer="Wurth Elektronik", Supplier Part Number 1=732-1621-1-ND, Value1="0.025 ohm", Value2=3A, ValueDisplayed="50 ohm"
L3: library part CMP-0056527-1, "Inductor, Unshielded Drum Core, Ferrite, 2.7 uH, 3.8 A, 0.055 ohm, AEC-Q200 Grade 1, SMD", Manufacturer=Bourns, Supplier Part Number 1=SDE0604A-2R7MCT-ND, Value1="0.055 ohm", Value2=3.8A, ValueDisplayed=2.7uH
L4: library part CMP-0058981-1, "Inductor, Shielded, 10 uH, 1.7 A, 0.2 ohm, AEC-Q200 Grade 1, SMD", Manufacturer="MuRata Toko", Value1="0.2 ohm", Value2=1.7A, ValueDisplayed=10uH
L5: library part CMP-0075677-1, "Ferrite Bead, 120 ohm @ 100 MHz, 0.4 A, 0402", Manufacturer=TDK, PartNumber=MMZ1005Y121CT000, Supplier Part Number 1=445-2152-1-ND, Value1="0.18 ohm", Value2=0.4A, ValueDisplayed="120 ohm"
L6: library part CMP-0062907-1, "Inductor, Shielded, Ferrite, 10 uH, 1.13 A, 0.237 ohm, SMD", Manufacturer=TDK, Supplier Part Number 1=445-3209-1-ND, Value1="0.237 ohm", Value2=1.13A, ValueDisplayed=10uH
L7 L8: library part CMP-0064361-1, "Inductor, Shielded, Powdered Iron, 4.7 uH, 1.5 A, 0.162 ohm, AEC-Q200 Grade 1, SMD", Manufacturer="Wurth Elektronik", Supplier Part Number 1=732-6941-1-ND, Value1="0.162 ohm", Value2=1.5A, ValueDisplayed=4.7uH
Logo1: library part CMP-0074844-1
Logo2: library part CMP-0074847-1, "FCC_disclaimer"
Logo3: library part CMP-0074838-1, "Texas Instrument Corporate Signature"
Logo4: library part CMP-0074769-1
MH1 MH2: library part CMP-0078422-2, "PCB Mounting Hole", Manufacturer=Any, PartNumber=N/A
Q1: library part CMP-0067550-1, "MOSFET, N-CH, 30 V, 5 A, AEC-Q101, DQK0006C (WSON-6)", Alternate Manufacturer=None, Manufacturer="Texas Instruments", Supplier Part Number 1=296-35548-1-ND, Value1="0.032 ohm", Value2="2.1 nC"
R1: library part CMP-0026518-2, "RES, 6.98 k, 1%, 0.063 W, AEC-Q200 Grade 0, 0402", Manufacturer=Vishay-Dale, Power_W=63mW, Supplier Part Number 1=541-6.98KLCT-ND, TempCo="100 ppm/C", Tolerance_%=1%, Value2=0.063W, Value_Code=6k98, ValueDisplayed=6.98k
R2: library part CMP-0026387-2, "RES, 45.3 k, 1%, 0.063 W, AEC-Q200 Grade 0, 0402", Manufacturer=Vishay-Dale, Power_W=63mW, Supplier Part Number 1=541-45.3KLCT-ND, TempCo="100 ppm/C", Tolerance_%=1%, Value2=0.063W, Value_Code=45k3, ValueDisplayed=45.3k
R3: library part CMP-0020844-3, "RES, 10.5 k, 1%, 0.125 W, AEC-Q200 Grade 0, 0805", Manufacturer=Vishay-Dale, Power_W=125mW, Supplier Part Number 1=541-10.5KCCT-ND, TempCo="100 ppm/C", Tolerance_%=1%, Value2=0.125W, Value_Code=10k5, ValueDisplayed=10.5k
R4: library part CMP-0026659-1, "RES, 100 k, 1%, 0.1 W, 0402", Manufacturer=Panasonic, Power_W=100mW, TempCo="100 ppm/C", Tolerance_%=1%, Value2=0.1W, Value_Code=100k
R5 R547: library part CMP-0026705-1, "RES, 51.0 k, 1%, 0.1 W, AEC-Q200 Grade 0, 0402", Manufacturer=Panasonic, Power_W=100mW, Supplier Part Number 1=P51.0KLCT-ND, TempCo="100 ppm/C", Tolerance_%=1%, Value2=0.1W, Value_Code=51k0, ValueDisplayed=51.0k
R6 R9 R14 R16 R512 R514 R515 R516 R517 R519 R520 R522 R523 R525 R526: library part CMP-0026696-1, "RES, 33.0, 1%, 0.1 W, 0402", Manufacturer=Panasonic, Power_W=100mW, Supplier Part Number 1=P33.0LCT-ND, TempCo="100 ppm/C", Tolerance_%=1%, Value2=0.1W, Value_Code=33R0, ValueDisplayed=33.0
R7 R8 R20 R21 R501 R502 R504 R505 R510 R513 R521 R524 R527 R528 R530 R531 R533 R536 R538 R539 R541 R542 R543 R544: library part CMP-0026994-4, "RES, 10 k, 5%, 0.1 W, AEC-Q200 Grade 0, 0402", Manufacturer=Panasonic, Power_W=100mW, Supplier Part Number 1=P10KJCT-ND, TempCo="200 ppm/C", Tolerance_%=5%, Value2=0.1W, Value_Code=10k0, ValueDisplayed=10k
R10 R11 R17 R506 R508 R532: library part CMP-0026681-1, "RES, 2.20 k, 1%, 0.1 W, 0402", Manufacturer=Panasonic, Power_W=100mW, Supplier Part Number 1=P2.20KLCT-ND, TempCo="100 ppm/C", Tolerance_%=1%, Value2=0.1W, Value_Code=2k20, ValueDisplayed=2.20k
R12 R13 R503: library part CMP-0021712-3, "RES, 42.2 k, 1%, 0.125 W, AEC-Q200 Grade 0, 0805", Manufacturer=Panasonic, Power_W=125mW, Supplier Part Number 1=P42.2KCCT-ND, TempCo="100 ppm/C", Tolerance_%=1%, Value2=0.125W, Value_Code=42k2, ValueDisplayed=42.2k
R15 R24 R25 R26 R529 R534: library part CMP-0078193-1, "RES, 1.0 k, 5%, 0.1 W, AEC-Q200 Grade 0, 0402", Manufacturer=Panasonic, Power_W=100mW, Supplier Part Number 1=P1.0KJCT-ND, TempCo="200 ppm/C", Tolerance_%=5%, Value2=0.1W, Value_Code=1k00, ValueDisplayed=1.0k
R18: library part CMP-0021666-2, "RES, 3.00 k, 1%, 0.125 W, AEC-Q200 Grade 0, 0805", Manufacturer=Panasonic, Power_W=125mW, Supplier Part Number 1=P3.0KCCT-ND, TempCo="100 ppm/C", Tolerance_%=1%, Value2=0.125W, Value_Code=3k00, ValueDisplayed=3.00k
R19: library part CMP-0020623-3, "RES, 1.0 M, 5%, 0.125 W, AEC-Q200 Grade 0, 0805", Manufacturer=Panasonic, Power_W=125mW, Supplier Part Number 1=P1.0MACT-ND, TempCo="150 ppm/C", Tolerance_%=5%, Value2=0.125W, Value_Code=1M00, ValueDisplayed=1.0M
R22 R23: library part CMP-0020744-3, "RES, 56, 5%, 0.125 W, AEC-Q200 Grade 0, 0805", Manufacturer=Panasonic, Power_W=125mW, Supplier Part Number 1=P56ACT-ND, TempCo="200 ppm/C", Tolerance_%=5%, Value2=0.125W, Value_Code=56R0, ValueDisplayed=56
R500 R511: library part CMP-0026695-1, "RES, 3.30 k, 1%, 0.1 W, AEC-Q200 Grade 0, 0402", Manufacturer=Panasonic, Power_W=100mW, Supplier Part Number 1=P3.30KLCT-ND, TempCo="100 ppm/C", Tolerance_%=1%, Value2=0.1W, Value_Code=3k30, ValueDisplayed=3.30k
R507 R509 R518 R535 R537 R540: library part CMP-0020766-3, "RES, 75, 5%, 0.125 W, AEC-Q200 Grade 0, 0805", Manufacturer=Panasonic, Power_W=125mW, Supplier Part Number 1=P75ACT-ND, TempCo="200 ppm/C", Tolerance_%=5%, Value2=0.125W, Value_Code=75R0, ValueDisplayed=75
R545: library part CMP-0022684-3, "RES, 10.0 k, 1%, 0.1 W, 0603", Manufacturer=Panasonic, Power_W=100mW, Supplier Part Number 1=P10.0KHCT-ND, TempCo="100 ppm/C", Tolerance_%=1%, Value2=0.1W, Value_Code=10k0, ValueDisplayed=10.0k
R546: library part CMP-0022695-3, "RES, 30.0 k, 1%, 0.1 W, AEC-Q200 Grade 0, 0603", Manufacturer=Panasonic, Power_W=100mW, Supplier Part Number 1=P30.0KHCT-ND, TempCo="100 ppm/C", Tolerance_%=1%, Value2=0.1W, Value_Code=30k0, ValueDisplayed=30.0k
TP1 TP2 TP3 TP4 TP5 TP6 TP7 TP8 TP9 TP10: library part CMP-0055152-1, "Test Point, Miniature, SMT", Manufacturer=Keystone, Supplier Part Number 1=36-5015TR-ND
U1: library part CMP-0076397-2, "Zero Iq Reverse Polarity Protection Smart Diode Controller, DGK0008A (VSSOP-8)", Alternate Manufacturer="Texas Instruments"
U2: library part CMP-0085279-3, "Automotive 65-V 1.5-A Synchronous Step-Down Converter, RNX0012B (VQFN-HR-12)", Alternate Manufacturer="Texas Instruments", Alternate PartNumber=LMR36015FSC3RNXRQ1
U3: library part CMP-0074076-5, "Automotive Catalog 1.2A Switch, High Voltage Boost Converter in 2x2mm QFN Package, DRV0006A (WSON-6)", Alternate Manufacturer="Texas Instruments"
U4: library part CMP-0750180-3, "DLP® System Management and Illumination Controller for DLP553x-Q1 Chipset, PZP0100K (TQFP-100)", Alternate Manufacturer="Texas Instruments", Operating Temperature Range="-40 to 105 C", Rating=Automotive
U5 U9 U10 U11 U501: library part CMP-0073599-3, "Automotive 4-Channel ESD Protection Solution for SuperSpeed (up to 5 Gbps) Interface, DQA0010A (USON-10)", Alternate Manufacturer="Texas Instruments"
U6: library part CMP-0050954-2, "Automotive Catalog Low-Voltage Single FET Bus Switch, DBV0005A (SOT-23-5)", F @ Nom Voltage(Max)(Mhz)=200, Generic Part Number=SN74CBTLV1G125-Q1, ICC @ Nom Voltage(Max)(mA)=0.01, Manufacturer="Texas Instruments", Operating Temperature Range="-40 to 125 C", Rating=Automotive, tpd @ Nom Voltage(Max)(ns)=0.25, Voltage(Nom)(V)=3.3
U7: library part CMP-0750177-3, "DLP® Automotive DMD Controller for DLP553x-Q1 Chipset, ZDQ0324 (BGA-324)", Alternate Manufacturer="Texas Instruments", Operating Temperature Range="-40 to 105 C", Rating=Automotive
U8: library part CMP-0860146-1, "Automotive Grade, Remote and Local Temperature Sensor with N-Factor and Series-R Correction, DGK0008A (VSSOP-8)", Alternate Manufacturer="Texas Instruments", Operating Temperature Range="-40 to 125 C", Rating=Automotive
U12: library part CMP-0080375-3, "Automotive 2.25-MHz Fixed VOUT Dual 800mA Step-Down Converter for ADAS Camera applications, DRC0010J (VSON-10)", Alternate Manufacturer="Texas Instruments", Operating Temperature Range="-40 to 125 C", Rating=Automotive
U500: library part CMP-0086504-1, "FLASH - NOR Memory IC 128Mb (16M x 8) SPI 133MHz  16-SOP2", Manufacturer=Micron
U502: library part CMP-0073595-1, "Automotive Dual-Channel High-Speed ESD Protection Device, DCK0003A (SOT-SC70-3)", Alternate Manufacturer="Texas Instruments"
Y1: library part CMP-0087311-1, "SMD SEAM SEALING X'TAL 3.2×2.5", Frequency_Fixed=16MHz, Frequency Stability=50ppm, Frequency Tolerance=10ppm, Load Capacitance=10pF, Manufacturer="TXC Corporation"
ZZ1: library part CMP-0077236-1
ZZ2: library part CMP-0077237-1
ZZ3: library part CMP-0077238-1

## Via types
v1: diameter 20, hole 10, Top Layer to Bottom Layer, tented both sides, 439 vias
v2: diameter 18, hole 8, Top Layer to Bottom Layer, tented both sides, 335 vias
v3: diameter 19.68, hole 7.87, Top Layer to Bottom Layer, tented both sides, 72 vias
v4: diameter 19.68, hole 7.87, Top Layer to Bottom Layer, tented bottom, 15 vias
v5: diameter 39.37, hole 19.68, Top Layer to Bottom Layer, 12 vias

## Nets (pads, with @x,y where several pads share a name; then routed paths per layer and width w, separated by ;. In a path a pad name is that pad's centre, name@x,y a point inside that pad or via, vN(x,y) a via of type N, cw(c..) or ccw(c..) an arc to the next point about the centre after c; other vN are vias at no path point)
1.1V: C55.1 C506.1 C509.1 C511.1 C513.1 C514.1 C516.1 C520.1 C523.1 C524.1 C529.1 C531.1 C534.1 C539.1 C540.1 C541.1 C542.1 C564.1 C565.1 FB501.1 FB505.1 FB508.1 FB510.1 L8.1 TP8.1 U4.98 U7.G4 U7.H19 U7.J11 U7.J19 U7.L4 U7.N19 U7.P19 U7.T4 U7.U4 U7.U19 U7.V19 U7.W6 U7.W8 U7.W10 U7.W16 U12.4 | length 1548.3
  Top Layer w10: U7.G4@3134.64,479.81 3144.64,489.81 v2(3144.64,507.65) ; U7.H19@3174.01,1070.36 v2(3193.69,1090.05) ; v2(3193.69,735.72) U7.J11@3213.38,755.4 ; U7.J19@3213.38,1070.36 v2(3233.06,1090.05) ; U7.L4@3292.12,479.81 3292.12,488.48 v2(3311.29,507.65) ; U7.N19@3370.86,1070.36 v2(3390.54,1090.05) ; v2(3410.23,1042.52) U7.P19@3410.23,1070.36 ; U7.T4@3488.97,479.81 v2(3488.97,507.65) ; U7.U4@3528.34,479.81 v2(3528.34,522.65) ; U7.U19@3528.34,1070.36 v2(3548.02,1090.05) U7.V19@3567.71,1070.36 ; v2(3579.24,637.29) U7.W8@3607.08,637.29 ; v2(3579.24,716.03) U7.W10@3607.08,716.03 ; v2(3579.24,952.25) U7.W16@3607.08,952.25 ; v2(3587.39,538.86) U7.W6@3607.08,558.55 ; 3991.1,1262.02 4004.72,1275.64 U12.4@4025.83,1275.64
  Top Layer w11.81: U4.98@1811.02,176.16 v1(1811.02,224.46)
  Bottom Layer w15: v1(2492.83,798.97) 2506.83,798.97 2527.44,778.36 C565.1@2567.4,778.36 2610.99,778.36 FB510.1@2627.37,761.98 ; v1(2566.26,624.36) 2575.26,615.36 C564.1@2597.02,615.36 2635.6,615.36 FB508.1@2646.98,603.98 ; C542.1@3143.19,1192.47 3168.09,1167.57 3168.09,1142.01 C539.1@3180.69,1129.42 3193.69,1116.42 v2(3193.69,1090.05) ; v2(3144.64,507.65) 3144.64,522.3 C540.1@3164.73,542.4 ; C541.1@3162.88,735.72 v2(3193.69,735.72) ; v2(3233.06,1090.05) C534.1@3233.06,1124.19 ; FB505.1@3248.67,903.55 3255.78,896.44 v2(3311.6,896.44) ; v2(3311.29,507.65) C531.1@3311.29,542.4 ; C529.1@3355.79,1090.05 v2(3390.54,1090.05) ; v2(3387.39,895.75) 3410.32,895.75 FB501.1@3435.02,871.05 ; v2(3410.23,1042.52) 3410.23,1022.59 C524.1@3425.07,1007.74 ; v2(3488.97,507.65) C523.1@3488.97,539.24 ; C520.1@3511.27,1090.05 v2(3548.02,1090.05) ; v2(3528.34,522.65) 3528.34,508.68 C509.1@3546.01,491.01 ; C514.1@3544.49,637.29 v2(3579.24,637.29) 3597.54,637.29 C506.1@3622.18,612.66 ; C513.1@3544.49,686.25 3549.46,686.25 v2(3579.24,716.03) ; C516.1@3544.49,961.84 3554.08,952.25 v2(3579.24,952.25) ; C511.1@3557.96,538.86 v2(3587.39,538.86)
  other v2: 3993.39,1073.2 3954.75,1192.64 3993.39,1192.64
1.8V: C28.1 C29.1 C30.1 C35.1 C36.1 C37.1 C40.1 C41.1 C43.1 C47.1 C54.1 C547.1 FB1.1 J500.A6 J500.A18 J500.B3 J500.B18 J500.C3 J500.D18 J500.E3 J500.E18 J500.F3 J500.G18 J500.H3 J500.H18 J500.J3 J500.K18 J500.L3 J500.L18 J500.M3 J500.M20 J500.N2 J500.R1 J500.R4 J500.R10 J500.R11 J500.R20 J500.T4 L7.1 TP9.1 U4.97 U7.D10 U12.1 | length 1468.5
  Top Layer w10: U7.D10@3016.53,716.03 v2(3036.21,696.35)
  Top Layer w11.81: v1(1791.34,127.86) U4.97@1791.34,176.16
  Top Layer w15: FB1.1@3108.54,1361.39 v2(3108.54,1404.31)
  Top Layer w20: v1(1537.99,1058.39) 1564.37,1032.01 C30.1@1569.8,1032.01 ; v1(1587.99,1358.39) 1587.99,1383.39 C28.1@1562.99,1408.39 1587.99,1433.39 v1(1587.99,1458.39) ; v1(1587.99,1758.39) C29.1@1587.99,1793.59 ; v1(1987.99,1008.39) C35.1@2019.85,1008.39 ; C36.1@2145.9,1008.39 v1(2177.76,1008.39) ; C37.1@2476.38,979.52 2477.76,980.9 v1(2477.76,1008.39) ; C41.1@2545.94,1408.39 v1(2577.76,1408.39) ; v1(2577.76,1708.39) C43.1@2577.76,1744.13 ; C40.1@2592.01,1158.39 v1(2627.76,1158.39) ; v1(2677.76,1058.39) 2708.19,1058.39 C47.1@2709.57,1057.01
  Bottom Layer w15: v2(3036.21,696.35) 3063.51,696.35 C547.1@3071.12,703.96
  Bottom Layer w20: v1(1487.99,1158.39) J500.M20@1512.99,1183.39 ; J500.R20@1512.99,1033.39 v1(1537.99,1058.39) ; v1(1587.99,1208.39) J500.L18@1612.99,1233.39 ; v1(1587.99,1258.39) J500.K18@1612.99,1283.39 ; v1(1587.99,1358.39) J500.H18@1612.99,1383.39 ; v1(1587.99,1458.39) J500.G18@1612.99,1433.39 ; v1(1587.99,1558.39) J500.E18@1612.99,1533.39 ; v1(1587.99,1608.39) J500.D18@1612.99,1583.39 ; v1(1587.99,1708.39) J500.B18@1612.99,1683.39 ; v1(1587.99,1758.39) J500.A18@1612.99,1733.39 ; J500.R11@1962.99,1033.39 v1(1987.99,1008.39) ; v1(2177.76,1008.39) J500.R10@2202.76,1033.39 ; v1(2377.76,1758.39) J500.A6@2402.76,1733.39 ; v1(2477.76,1008.39) J500.T4@2502.76,983.39 ; J500.R4@2502.76,1033.39 v1(2527.76,1058.39) ; J500.M3@2552.76,1183.39 v1(2577.76,1208.39) ; J500.L3@2552.76,1233.39 v1(2577.76,1258.39) ; J500.J3@2552.76,1333.39 v1(2577.76,1358.39) ; J500.H3@2552.76,1383.39 v1(2577.76,1408.39) ; J500.F3@2552.76,1483.39 v1(2577.76,1508.39) ; J500.E3@2552.76,1533.39 v1(2577.76,1558.39) ; J500.C3@2552.76,1633.39 v1(2577.76,1658.39) ; J500.B3@2552.76,1683.39 v1(2577.76,1708.39) ; J500.N2@2602.76,1133.39 v1(2627.76,1158.39) ; J500.R1@2652.76,1033.39 v1(2677.76,1058.39)
  other v2: 3993.39,1386.19 3954.75,1505.63 3993.39,1505.63
3.3V: C7.1 C14.1 C15.1 C34.1 C52.1 C53.1 C500.1 C503.1 C504.1 C525.1 C527.1 C528.1 C530.1 C532.1 C533.1 C536.1 C537.1 C566.1 C575.1 C576.1 C578.1 FB500.1 FB506.1 L3.2 L5.1 L6.1 R10.2 R15.2 R17.2 R25.2 R26.2 R500.2 R501.2 R502.2 R504.2 R506.2 R508.2 R510.2 R511.2 R524.2 R531.2 R533.2 R534.2 R536.2 TP2.1 U2.7 U3.5 U3.6 U4.14 U4.26 U4.36 U4.96 U6.2 U6.5 U7.G19 U7.H4 U7.J4 U7.K4 U7.K19 U7.L19 U7.M4 U7.M19 U7.N4 U7.P4 U7.R19 U7.T19 U7.V4 U7.W4 U7.W5 U8.1 U12.3 U500.2 | length 2900
  Top Layer w9.45: 3980.55,1289.77 3991.12,1289.77 3996.67,1295.32 U12.3@4025.83,1295.32
  Top Layer w10: v1(823.54,493.39) 846.76,493.39 861.01,479.14 U2.7@861.01,473.05 ; U3.6@1173.39,1714.09 U3.5@1173.39,1688.5 1188.74,1688.5 1192.81,1692.58 1192.81,1710.75 ; 1246.4,1835.08 1288.66,1835.08 L6.1@1325,1798.74 1361.34,1835.08 1403.6,1835.08 ; U4.26@1850.39,782.46 1850.39,762.23 1865.07,747.56 ; U7.G19@3134.64,1070.36 v2(3154.32,1090.05) ; U7.H4@3174.01,479.81 v2(3174.01,507.65) ; U7.J4@3213.38,479.81 v2(3213.38,507.65) ; U7.K4@3252.75,479.81 3252.75,497.96 v2(3262.44,507.65) ; U7.K19@3252.75,1070.36 v2(3272.43,1050.68) ; U7.L19@3292.12,1070.36 v2(3311.8,1050.68) ; U7.M4@3331.49,479.81 v2(3351.17,499.49) ; U7.M19@3331.49,1070.36 v2(3351.17,1050.68) ; U7.N4@3370.86,479.81 v2(3390.54,499.49) U7.P4@3410.23,479.81 ; v2(3449.6,1042.52) U7.R19@3449.6,1070.36 ; v2(3488.97,1042.52) U7.T19@3488.97,1070.36 ; v2(3548.02,460.12) U7.V4@3567.71,479.81 ; U7.W4@3607.08,479.81 v2(3626.76,499.49) ; U7.W5@3607.08,519.18 v2(3626.76,538.86)
  Top Layer w11.81: U4.36@1653.54,782.46 1653.54,829.81 ; U4.96@1771.65,176.16 v1(1771.65,224.46) ; U4.14@1917.32,498.99 1958.66,498.99 1966.26,506.6
  Top Layer w15: 1653.54,829.81 v1(1653.54,845.28) ; 1966.26,506.6 1972.44,512.77 C34.1@1988.91,512.77 v1(2018.72,512.77) ; v1(2434.51,421.14) 2434.51,390.39 R15.2@2439.51,385.39 ; v1(2482.41,574.25) 2508.16,574.25 U6.5@2513.16,569.25 ; U6.2@2550.56,460.98 v1(2550.56,501.69) ; v1(2629.3,419.14) 2629.3,394.57 R17.2@2638.48,385.39 ; U8.1@3148.57,1598.77 3158.47,1598.77 3194.7,1635 C52.1@3194.7,1651.82 v2(3194.7,1683.17) ; v2(3428.33,1529.04) R26.2@3428.33,1560.39 ; R25.2@3428.33,1614.28 v2(3428.33,1645.63) ; v2(3864.05,1262.84) C53.1@3914.55,1262.84 3926.54,1262.84 3953.46,1289.77 3980.55,1289.77
  Top Layer w20: v1(1070.19,497.48) L5.1@1110.31,497.48 ; 1865.07,747.56 v1(1875.17,737.45) ; R10.2@2052.53,512.77 v1(2084.34,512.77)
  Split PWR 2 w10: v2(3074.9,785.95) 3074.9,774.4 3084.18,765.12 ; 3134.82,636.28 3134.82,641.91 v2(3146.99,654.08) ; v2(3154.32,1090.05) 3154.32,1073.41 3158.2,1069.53
  Bottom Layer w15: R536.2@2348.26,601.75 v1(2348.26,636.36) ; v1(2414.93,167.52) 2425.23,167.52 2448.37,144.38 R534.2@2451.52,144.38 ; v1(2482.41,574.25) 2508.16,574.25 C566.1@2513.16,569.25 ; R533.2@2540.39,469.88 2550.56,480.05 v1(2550.56,501.69) ; v1(2637.18,446.54) 2643.6,452.95 R531.2@2672.81,452.95 ; v2(3074.9,785.95) FB506.1@3074.9,824.74 ; R524.2@3112.24,654.08 v2(3146.99,654.08) ; C537.1@3154.32,1059.24 v2(3154.32,1090.05) ; v2(3213.38,507.65) C536.1@3213.38,542.19 ; v2(3262.44,507.65) C533.1@3262.44,542.4 ; v2(3272.43,1050.68) 3272.43,1012.74 C532.1@3277.43,1007.74 ; v2(3311.8,1050.68) 3311.8,1022.59 C530.1@3326.64,1007.74 ; v2(3351.17,499.49) 3360.14,508.47 C528.1@3360.14,542.4 ; v2(3351.17,1050.68) 3351.17,1032.43 C527.1@3375.86,1007.74 ; v2(3390.54,499.49) 3390.54,523.94 C525.1@3408.99,542.4 ; v2(3448.15,1903.81) R510.2@3482.89,1903.81 ; R511.2@3482.89,1603.81 v2(3482.89,1638.56) ; v2(3626.76,499.49) 3653.26,499.49 C504.1@3661.76,490.99 ; v2(3626.76,538.86) 3628.26,540.36 C503.1@3661.76,540.36 ; R508.2@3741.58,658.61 v2(3770.39,658.61) ; FB500.1@3748.81,973.94 3753.81,978.94 v2(3787.49,978.94) ; v2(3754.8,524.18) 3783.91,524.18 R506.2@3790.72,530.99 ; U500.2@3971.08,1903.81 C500.1@4051.79,1903.81 v2(4051.79,1869.07) ; v2(4099.04,1569.07) R502.2@4099.04,1603.81 ; R501.2@4099.04,1653.81 v2(4099.04,1688.56) ; R500.2@4099.04,1953.81 v2(4133.78,1953.81)
  Bottom Layer w20: C578.1@1653.54,804.53 v1(1653.54,845.28) ; v1(1875.17,737.45) C576.1@1906.98,737.45 1915.77,737.45 1938.85,760.53 C575.1@1977.07,760.53 ; R504.2@3829.66,196.57 v1(3829.66,232.32)
  other v1: 636.98,66.38 1124.8,66.38 636.98,115.91 1124.8,115.91 1168.41,1874.55 1215.41,1874.55 1262.41,1874.55 1168.41,1922.4 1215.41,1922.4 1262.41,1922.4
6.5V: C16.1 C19.1 C21.1 C24.1 C579.1 C580.1 C582.1 C583.1 C584.1 D4.1 R2.2 TP5.1 U4.42 U4.55 U4.65 U4.67 U4.79 | length 758.7
  Top Layer w11.81: U4.67@1311.02,400.57 1262.43,400.57 1247.54,415.47 v1(1247.54,429.26) 1264.47,429.26 1275.14,439.94 U4.65@1311.02,439.94 ; U4.55@1311.02,636.79 v1(1359.32,636.79) ; 1427.95,122.04 1427.95,133.96 1437.01,143.02 U4.79@1437.01,176.16 ; U4.42@1535.43,782.46 1535.43,824.81
  Top Layer w15: 1535.43,824.81 v1(1535.43,840.28)
  Top Layer w20: v1(933.44,1726.09) R2.2@969.19,1726.09 ; v1(1207.85,376.69) C19.1@1207.85,413.39 1223.73,429.26 v1(1247.54,429.26) ; v1(1414.01,50.46) C24.1@1414.01,89.16 1427.95,103.1 1427.95,122.04
  Bottom Layer w15: C582.1@1312.24,585.74 C584.1@1312.24,648.75 1347.36,648.75 v1(1359.32,636.79)
  Bottom Layer w20: C583.1@1247.54,390.52 v1(1247.54,429.26) ; v1(1535.43,840.28) C580.1@1535.43,804.53 C579.1@1593.2,804.53
  other v1: 1122.12,1406.92 1172.84,1406.92 1223.55,1406.92
11SW1: L8.2 U12.6 | length 25.8
  Top Layer w9: U12.6@4136.06,1255.95 4146.38,1255.95 4157.34,1245
18SW2: L7.2 U12.10 | length 28
  Top Layer w9: U12.10@4136.06,1334.69 4146.42,1334.69 4158.88,1347.15
33SW: C12.2 L3.1 U2.3 U2.12 | length 270.9
  Top Layer w10: 880.7,330.58 U2.12@880.7,386.91 880.7,415.75 889.77,424.82 U2.3@916.13,424.82 949.43,424.82 C12.2@964,439.39
  Top Layer w20: 880.7,293.82 880.7,330.58
  Top Layer w40: L3.1@880.7,237.93 880.7,293.82
65SW: D4.2 L6.2 U3.4 | length 187.3
  Top Layer w10: 1246.4,1626.57 1288.66,1626.57 L6.2@1325,1662.91 1361.34,1626.57 1403.6,1626.57
\DMD_DEN_ARST: J500.T10 R11.2 U7.D11 | length 1315.1
  Top Layer w6.2: v1(2202.76,948.03) 2219.4,931.39 2234.05,931.39 R11.2@2252.76,912.68 2286.22,879.21 2286.22,680.51 v1(2311.95,654.79) ; U7.D11@3016.53,755.4 v2(3036.21,735.72)
  Bottom Layer w6.2: v1(2202.76,948.03) J500.T10@2202.76,983.39 ; v1(2311.95,654.79) 2322.26,665.1 2472.5,665.1 2563.4,574.2 2745.15,574.2 2755.45,563.9 2832.89,563.9 2852.48,583.49 2852.48,621.15 2868.59,637.26 3008.03,637.26 3016.57,645.79 3016.57,716.07 v2(3036.21,735.72)
\HOLD_BOOT: C39.1 J3.4 R533.1 U6.1 U501.4 | length 424.9
  Top Layer w6.2: U6.1@2513.16,460.98 2516.17,457.98 v1(2516.17,423.3) 2516.17,360.45 C39.1@2538.48,338.14 2572.6,304.02 2595.33,304.02 2622.5,276.86 v1(2627.95,276.86) J3.4@2627.95,229.33
  Bottom Layer w6.2: R533.1@2493.15,469.88 2516.17,446.86 v1(2516.17,423.3) ; v1(2627.95,276.86) 2627.95,316.14 2639.27,327.45 U501.4@2639.27,345.27
\HOST_SPI_CS: R535.2 R536.1 U7.W20 | length 3258
  Top Layer w6.2: U7.W20@3607.08,1109.73 v2(3626.76,1129.42)
  Signal Layer 1 w5.6: v1(2380.07,554.51) 2299.04,473.48 2084.78,473.48 1998.41,387.1 1998.41,268.42 2191.69,75.14 2976.63,75.14 3006.18,104.69 3249.84,104.69 3386.9,241.74 3386.9,342.55 3468.47,424.12 3503.6,424.12 3528.2,448.72 3528.2,486.83 3561.28,519.91 3561.28,582.93 3602.38,624.03 3602.38,747.98 3646.61,792.21 3646.61,1109.57 v2(3626.76,1129.42)
  Bottom Layer w6.2: R535.2@2348.26,487.49 R536.1@2348.26,554.51 v1(2380.07,554.51)
\HOST_SPI_CS_S: C569.1 J2.7 R535.1 U5.5 | length 304.7
  Top Layer w6.2: U5.5@2263.78,355.21 2263.78,347.73 2270.4,341.11 2278.27,341.11 v1(2342.52,276.86) J2.7@2342.52,229.33
  Bottom Layer w6.2: v1(2342.52,276.86) 2342.52,302.55 2332.16,312.91 C569.1@2332.16,344.27 2332.16,391.39 R535.1@2348.26,407.49
\PMIC_SPI2_CS: R504.1 R507.2 U4.33 | length 2921.7
  Top Layer w6.2: v1(1692.91,734.16) 1706.05,734.16 1712.6,740.71 U4.33@1712.6,782.46
  Signal Layer 2 w5.6: v1(1692.91,734.16) 1692.91,477.72 1718.62,452.01 1840.71,452.01 1940.84,351.87 1940.84,163.71 2071.03,33.52 2999.02,33.52 3035.23,69.74 3157.73,69.74 3193.37,34.09 3579.21,34.09 3656.39,111.27 v1(3829.66,111.27)
  Bottom Layer w6.2: R507.2@3759.34,149.33 R504.1@3829.66,149.33 v1(3829.66,111.27)
\PMIC_SPI2_CS_S: C505.1 J5.7 R507.1 | length 155.9
  Top Layer w6.2: J5.7@3602.36,229.33 v1(3655.73,229.33)
  Bottom Layer w6.2: v1(3655.73,229.33) C505.1@3686.46,229.33 ; C505.1@3687.54,229.33 R507.1@3759.34,229.33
